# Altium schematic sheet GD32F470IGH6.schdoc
size 127 x 101 mm
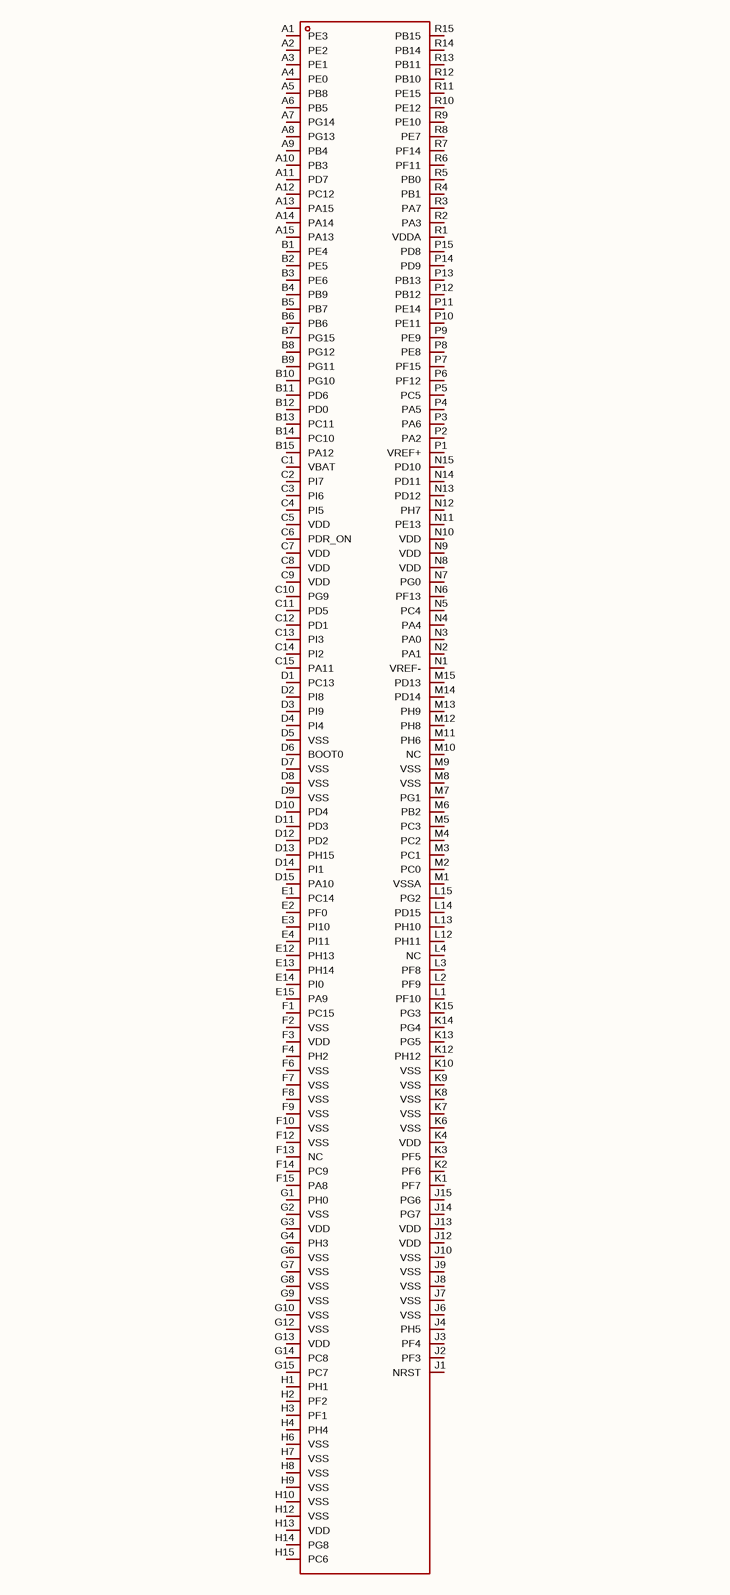
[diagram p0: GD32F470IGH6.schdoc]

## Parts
U?  gd32f470igh6  [BGA-201_L10.0-W10.0-P0.65-TL_GD32F450IGH6]  (value not drawn)

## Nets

Not connected (* = marked no-connect by the designer): U? A1(PE3) A2(PE2) A3(PE1) A4(PE0) A5(PB8) A6(PB5) A7(PG14) A8(PG13) A9(PB4) A10(PB3) A11(PD7) A12(PC12) A13(PA15) A14(PA14) A15(PA13) B1(PE4) B2(PE5) B3(PE6) B4(PB9) B5(PB7) B6(PB6) B7(PG15) B8(PG12) B9(PG11) B10(PG10) B11(PD6) B12(PD0) B13(PC11) B14(PC10) B15(PA12) C1(VBAT) C2(PI7) C3(PI6) C4(PI5) C5(VDD) C6(PDR_ON) C7(VDD) C8(VDD) C9(VDD) C10(PG9) C11(PD5) C12(PD1) C13(PI3) C14(PI2) C15(PA11) D1(PC13) D2(PI8) D3(PI9) D4(PI4) D5(VSS) D6(BOOT0) D7(VSS) D8(VSS) D9(VSS) D10(PD4) D11(PD3) D12(PD2) D13(PH15) D14(PI1) D15(PA10) E1(PC14) E2(PF0) E3(PI10) E4(PI11) E12(PH13) E13(PH14) E14(PI0) E15(PA9) F1(PC15) F2(VSS) F3(VDD) F4(PH2) F6(VSS) F7(VSS) F8(VSS) F9(VSS) F10(VSS) F12(VSS) F13(NC) F14(PC9) F15(PA8) G1(PH0) G2(VSS) G3(VDD) G4(PH3) G6(VSS) G7(VSS) G8(VSS) G9(VSS) G10(VSS) G12(VSS) G13(VDD) G14(PC8) G15(PC7) H1(PH1) H2(PF2) H3(PF1) H4(PH4) H6(VSS) H7(VSS) H8(VSS) H9(VSS) H10(VSS) H12(VSS) H13(VDD) H14(PG8) H15(PC6) J1(NRST) J2(PF3) J3(PF4) J4(PH5) J6(VSS) J7(VSS) J8(VSS) J9(VSS) J10(VSS) J12(VDD) J13(VDD) J14(PG7) J15(PG6) K1(PF7) K2(PF6) K3(PF5) K4(VDD) K6(VSS) K7(VSS) K8(VSS) K9(VSS) K10(VSS) K12(PH12) K13(PG5) K14(PG4) K15(PG3) L1(PF10) L2(PF9) L3(PF8) L4(NC) L12(PH11) L13(PH10) L14(PD15) L15(PG2) M1(VSSA) M2(PC0) M3(PC1) M4(PC2) M5(PC3) M6(PB2) M7(PG1) M8(VSS) M9(VSS) M10(NC) M11(PH6) M12(PH8) M13(PH9) M14(PD14) M15(PD13) N1(VREF-) N2(PA1) N3(PA0) N4(PA4) N5(PC4) N6(PF13) N7(PG0) N8(VDD) N9(VDD) N10(VDD) N11(PE13) N12(PH7) N13(PD12) N14(PD11) N15(PD10) P1(VREF+) P2(PA2) P3(PA6) P4(PA5) P5(PC5) P6(PF12) P7(PF15) P8(PE8) P9(PE9) P10(PE11) P11(PE14) P12(PB12) P13(PB13) P14(PD9) P15(PD8) R1(VDDA) R2(PA3) R3(PA7) R4(PB1) R5(PB0) R6(PF11) R7(PF14) R8(PE7) R9(PE10) R10(PE12) R11(PE15) R12(PB10) R13(PB11) R14(PB14) R15(PB15)

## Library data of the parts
U? = gd32f470igh6: CPU内核:ARM Cortex-M4;CPU最大主频:240MHz;CPU位数:32 Bit;; Manufacturer: GigaDevice(兆易创新); AddInBom: yes; ModelId: 88402b30fb10484d82a979771f4363d0; ModelName: UFBGA-201_L10.0-W10.0-H0.5-P0.65-TL_STM32H743IIK6; ModelTransform: 393.7,393.7,0,0,0,0,0,0,0; CPU Maximum Speed: 240MHz; Core Size: 32 Bit; Program Storage Size: 1MB; Program Memory Type: FLASH; RAM Size: 512KB; Number of I/O: 140; ADC (Bit): 12bit; Oscillator Type: 内置+外置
